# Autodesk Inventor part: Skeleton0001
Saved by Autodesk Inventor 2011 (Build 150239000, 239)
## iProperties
Created: 2020-12
Part Number: Skeleton0001
Document SubType Name: Modeling
Designer: PC
Density: 1 g/cm^3
_SkeletonDoc: Frame Skeleton File
_Version: 15.0.0
Author: PC
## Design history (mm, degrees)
sketch "Reference Skeleton"
